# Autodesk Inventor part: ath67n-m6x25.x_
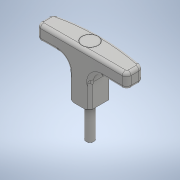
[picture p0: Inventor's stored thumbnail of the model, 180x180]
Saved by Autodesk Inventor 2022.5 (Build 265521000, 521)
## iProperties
Part Number: ath67n-m6x25.x_
Material: 一般
Document SubType Name: Modeling
Designer: ImaoCorp
Density: 1 g/cm^3
Appearance: 既定
Sending System: SOLIDWORKS 2017-2017317
MC: AMD64
MC_MODEL: Intel64 Family 6 Model 60 Stepping 3, GenuineIntel
OS: Windows_NT
FRU: Parasolid Version 29.0, build 201,  4-17-2017
FORMAT: text
GUISE: transmit
KEY: ath67n-m6x25
FILE: ath67n-m6x25.x_t
DATE: Tue Feb 05 16:17:57 2019
Author: ImaoCorp
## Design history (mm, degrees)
feature "Base1"
node "ソリッド1"
